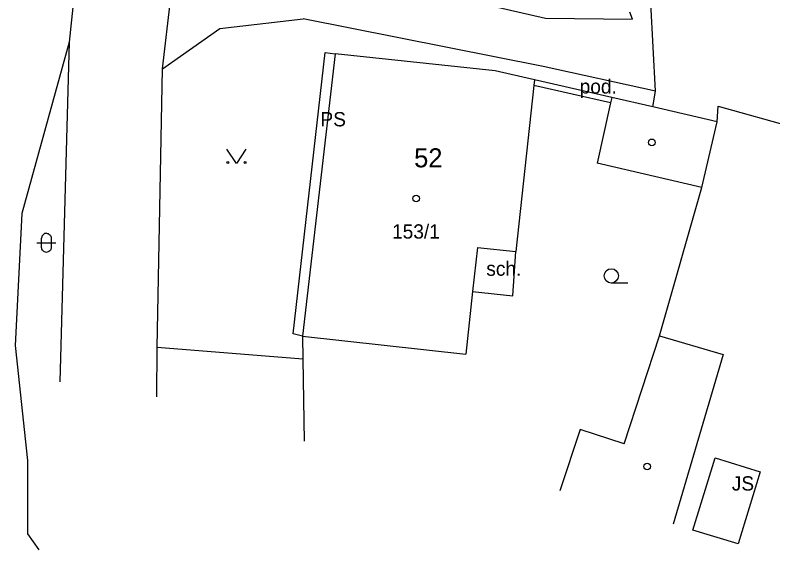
# Model space of a CAD drawing. Extents: x -836739 to -835945, y -1070775 to -1070126.
# Drawn here: x -836661.26 to -836621.48, y -1070507.95 to -1070479.9 of the extents above; entities that cross this region are included whole.
import ezdxf

# ---------------------------------------------------------------- set-up
doc = ezdxf.new("R2010")
doc.units = 0
for name, color, linetype in [('BodPole_mer', 7, 'Continuous'), ('Budovy_hranice', 7, 'Continuous'), ('Budovy_kody', 7, 'Continuous'), ('Doprava_hranice', 7, 'Continuous'), ('OstPloch_hranice', 7, 'Continuous'), ('OstPloch_kody', 7, 'Continuous'), ('RuianAdr_popis', 7, 'Continuous'), ('RuianPar_popis', 7, 'Continuous'), ('Stavby_hr_schod', 7, 'Continuous'), ('Stavby_hr_stav', 7, 'Continuous'), ('Stavby_kody', 7, 'Continuous'), ('Stavby_linie', 7, 'Continuous'), ('Zelen_kody', 7, 'Continuous')]:
    doc.layers.add(name, color=color, linetype=linetype)

msp = doc.modelspace()

# ---------------------------------------------------------------- linework, layer by layer
at = {"layer": 'BodPole_mer'}
for p, q in [((-836646.14, -1070480.08), (-836646.14, -1070480.08)), ((-836633.42, -1070480.06), (-836633.42, -1070480.06)), ((-836628.84, -1070480.11), (-836628.84, -1070480.11)), ((-836650.51, -1070480.59), (-836650.51, -1070480.59)), ((-836658.42, -1070481.32), (-836658.42, -1070481.32)), ((-836644.99, -1070481.86), (-836644.99, -1070481.86)), ((-836644.45, -1070481.92), (-836644.45, -1070481.92)), ((-836633.54, -1070482.59), (-836633.54, -1070482.59)), ((-836653.53, -1070482.71), (-836653.53, -1070482.71)), ((-836636.06, -1070482.82), (-836636.06, -1070482.82)), ((-836633.99, -1070483.29), (-836633.99, -1070483.29)), ((-836634.02, -1070483.59), (-836634.02, -1070483.59)), ((-836629.93, -1070484.21), (-836629.93, -1070484.21)), ((-836627.64, -1070483.88), (-836627.64, -1070483.88)), ((-836630, -1070484.5), (-836630, -1070484.5)), ((-836627.77, -1070484.71), (-836627.77, -1070484.71)), ((-836624.35, -1070484.67), (-836624.35, -1070484.67)), ((-836624.4, -1070485.49), (-836624.4, -1070485.49)), ((-836630.7, -1070487.66), (-836630.7, -1070487.66)), ((-836625.2, -1070488.93), (-836625.2, -1070488.93)), ((-836660.91, -1070490.3), (-836660.91, -1070490.3)), ((-836636.98, -1070492.08), (-836636.98, -1070492.08)), ((-836634.97, -1070492.3), (-836634.97, -1070492.3)), ((-836637.24, -1070494.39), (-836637.24, -1070494.39)), ((-836635.12, -1070494.62), (-836635.12, -1070494.62)), ((-836646.67, -1070496.62), (-836646.67, -1070496.62)), ((-836646.18, -1070496.73), (-836646.18, -1070496.73)), ((-836627.42, -1070496.72), (-836627.42, -1070496.72)), ((-836637.6, -1070497.68), (-836637.6, -1070497.68)), ((-836624.09, -1070497.7), (-836624.09, -1070497.7)), ((-836646.16, -1070497.95), (-836646.16, -1070497.95)), ((-836631.6, -1070501.63), (-836631.6, -1070501.63)), ((-836629.28, -1070502.39), (-836629.28, -1070502.39)), ((-836624.5, -1070503.12), (-836624.5, -1070503.12)), ((-836622.14, -1070503.85), (-836622.14, -1070503.85))]:
    msp.add_line(p, q, dxfattribs=at)
at = {"layer": 'Budovy_hranice'}
for p, q in [((-836644.45, -1070481.92), (-836646.18, -1070496.73)), ((-836636.06, -1070482.82), (-836644.45, -1070481.92)), ((-836633.99, -1070483.29), (-836636.06, -1070482.82)), ((-836625.2, -1070488.93), (-836624.4, -1070485.49)), ((-836625.2, -1070488.93), (-836630.7, -1070487.66)), ((-836636.98, -1070492.08), (-836634.97, -1070492.3)), ((-836646.18, -1070496.73), (-836637.6, -1070497.68)), ((-836629.28, -1070502.39), (-836627.42, -1070496.72)), ((-836627.42, -1070496.72), (-836624.09, -1070497.7)), ((-836624.09, -1070497.7), (-836626.71, -1070506.61)), ((-836631.6, -1070501.63), (-836632.66, -1070504.86)), ((-836629.28, -1070502.39), (-836631.6, -1070501.63))]:
    msp.add_line(p, q, dxfattribs=at)
for points in [[(-836633.99, -1070483.29), (-836634.02, -1070483.59), (-836634.97, -1070492.3)], [(-836629.93, -1070484.21), (-836630, -1070484.5), (-836630.7, -1070487.66)], [(-836624.4, -1070485.49), (-836627.77, -1070484.71), (-836629.93, -1070484.21)], [(-836636.98, -1070492.08), (-836637.24, -1070494.39), (-836637.6, -1070497.68)]]:
    msp.add_lwpolyline(points, dxfattribs=at)
at = {"layer": 'Budovy_kody'}
for centre in [(-836627.83, -1070486.57), (-836640.2, -1070489.51), (-836628.07, -1070503.58)]:
    msp.add_circle(centre, 0.175, dxfattribs=at)
at = {"layer": 'Doprava_hranice'}
for p, q in [((-836657.15, -1070469.1), (-836658.42, -1070481.32)), ((-836653.53, -1070482.71), (-836652.59, -1070474.71)), ((-836644.54, -1070477.48), (-836633.42, -1070480.06)), ((-836628.84, -1070480.11), (-836628.99, -1070479.73)), ((-836650.51, -1070480.59), (-836646.14, -1070480.08)), ((-836633.54, -1070482.59), (-836646.14, -1070480.08)), ((-836633.42, -1070480.06), (-836628.84, -1070480.11)), ((-836653.53, -1070482.71), (-836650.51, -1070480.59)), ((-836658.42, -1070481.32), (-836658.91, -1070499.14)), ((-836627.64, -1070483.88), (-836633.54, -1070482.59)), ((-836646.16, -1070497.95), (-836653.81, -1070497.34))]:
    msp.add_line(p, q, dxfattribs=at)
msp.add_lwpolyline([(-836653.82, -1070499.93), (-836653.81, -1070497.34), (-836653.53, -1070482.71)], dxfattribs=at)
at = {"layer": 'OstPloch_hranice'}
msp.add_line((-836627.42, -1070496.72), (-836625.2, -1070488.93), dxfattribs=at)
msp.add_lwpolyline([(-836658.42, -1070481.32), (-836660.91, -1070490.3), (-836661.26, -1070497.22), (-836660.61, -1070503.27), (-836660.62, -1070507.11), (-836660.01, -1070507.95)], dxfattribs=at)
at = {"layer": 'OstPloch_kody'}
for p, q in [((-836659.87, -1070492.09), (-836659.87, -1070491.59)), ((-836659.37, -1070491.59), (-836659.37, -1070492.09)), ((-836660.12, -1070491.84), (-836659.12, -1070491.84)), ((-836629.085, -1070493.95), (-836629.96, -1070493.95))]:
    msp.add_line(p, q, dxfattribs=at)
for points in [[(-836659.62, -1070491.34), (-836659.665, -1070491.344), (-836659.712, -1070491.358), (-836659.757, -1070491.381), (-836659.797, -1070491.413), (-836659.829, -1070491.453), (-836659.852, -1070491.498), (-836659.866, -1070491.545), (-836659.87, -1070491.59)], [(-836659.62, -1070491.34), (-836659.575, -1070491.344), (-836659.528, -1070491.358), (-836659.483, -1070491.381), (-836659.443, -1070491.413), (-836659.411, -1070491.453), (-836659.388, -1070491.498), (-836659.374, -1070491.545), (-836659.37, -1070491.59)], [(-836659.62, -1070492.34), (-836659.665, -1070492.336), (-836659.712, -1070492.322), (-836659.757, -1070492.299), (-836659.797, -1070492.267), (-836659.829, -1070492.227), (-836659.852, -1070492.182), (-836659.866, -1070492.135), (-836659.87, -1070492.09)], [(-836659.37, -1070492.09), (-836659.374, -1070492.135), (-836659.388, -1070492.182), (-836659.411, -1070492.227), (-836659.443, -1070492.267), (-836659.483, -1070492.299), (-836659.528, -1070492.322), (-836659.575, -1070492.336), (-836659.62, -1070492.34)]]:
    msp.add_lwpolyline(points, dxfattribs=at)
msp.add_ellipse((-836629.96, -1070493.575), major_axis=(0.375, 0), ratio=0.999999, dxfattribs=at)
at = {"layer": 'RuianAdr_popis'}
msp.add_line((-836640.31, -1070487.88), (-836640.31, -1070487.88), dxfattribs=at)
at = {"layer": 'RuianPar_popis'}
msp.add_line((-836641.47, -1070491.62), (-836641.47, -1070491.62), dxfattribs=at)
at = {"layer": 'Stavby_hr_schod'}
msp.add_lwpolyline([(-836637.24, -1070494.39), (-836635.12, -1070494.62), (-836634.97, -1070492.3)], dxfattribs=at)
at = {"layer": 'Stavby_hr_stav'}
msp.add_line((-836629.93, -1070484.21), (-836633.99, -1070483.29), dxfattribs=at)
for points in [[(-836646.18, -1070496.73), (-836646.67, -1070496.62), (-836644.99, -1070481.86), (-836644.45, -1070481.92)], [(-836623.3, -1070507.63), (-836625.67, -1070506.91), (-836624.5, -1070503.12), (-836622.14, -1070503.85), (-836623.3, -1070507.63)]]:
    msp.add_lwpolyline(points, dxfattribs=at)
at = {"layer": 'Stavby_linie'}
msp.add_line((-836630, -1070484.5), (-836634.02, -1070483.59), dxfattribs=at)
for points in [[(-836627.77, -1070484.71), (-836627.64, -1070483.88), (-836627.88, -1070479.26), (-836628.79, -1070478.81)], [(-836624.4, -1070485.49), (-836624.35, -1070484.67), (-836620.34, -1070485.79)], [(-836646.18, -1070496.73), (-836646.16, -1070497.95), (-836646.09, -1070502.25)]]:
    msp.add_lwpolyline(points, dxfattribs=at)
at = {"layer": 'Zelen_kody'}
msp.add_lwpolyline([(-836649.14, -1070486.93), (-836649.64, -1070487.68), (-836650.14, -1070486.93)], dxfattribs=at)
for centre in [(-836650.089, -1070487.63), (-836649.189, -1070487.63)]:
    msp.add_circle(centre, 0.05, dxfattribs=at)

# ---------------------------------------------------------------- texts
at = {"layer": 'RuianAdr_popis'}
msp.add_text('52', height=1, dxfattribs=at).set_placement((-836640.31, -1070487.88))
at = {"layer": 'RuianPar_popis'}
msp.add_text('153/1', height=0.75, dxfattribs=at).set_placement((-836641.47, -1070491.62))
at = {"layer": 'Stavby_kody'}
for s, p in [('pod.', (-836631.62, -1070484.01)), ('PS', (-836645.23, -1070485.73)), ('sch.', (-836636.52, -1070493.57)), ('JS', (-836623.63, -1070504.84))]:
    msp.add_text(s, height=0.75, dxfattribs=at).set_placement(p)

doc.saveas('drawing.dxf')
